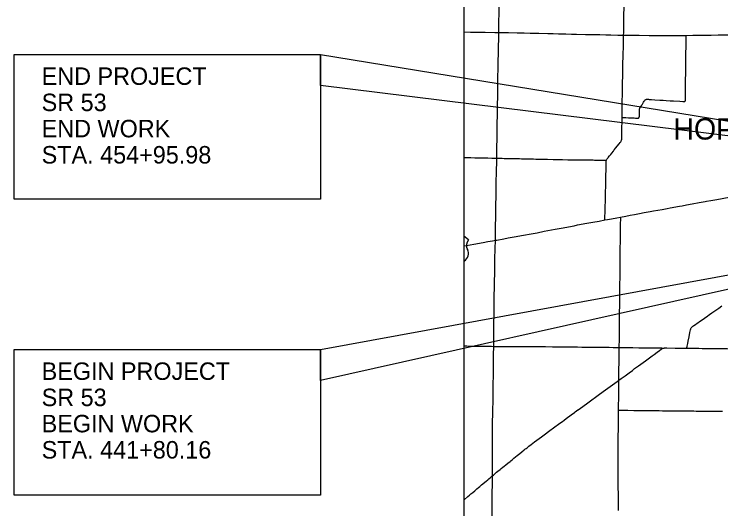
# Model space of a CAD drawing. Extents: x 1772825 to 1773716, y 1138558 to 1139032.
# Drawn here: x 1773161.2 to 1773274.4, y 1138810.8 to 1138890.1 of the extents above; entities that cross this region are included whole.
import ezdxf

# ---------------------------------------------------------------- set-up
doc = ezdxf.new("R2010")
doc.units = 0
for name, color, linetype in [('GM_X_County', 7, 'Continuous'), ('GM_X_County_Road', 7, 'Continuous'), ('GM_X_Township_Road', 7, 'Continuous'), ('GM_X_Township_Text', 7, 'Continuous'), ('GM_X_US_Route', 7, 'Continuous'), ('GM_X_US_Shield', 7, 'Continuous'), ('SH_Text', 7, 'Continuous')]:
    doc.layers.add(name, color=color, linetype=linetype)

msp = doc.modelspace()

# ---------------------------------------------------------------- linework, layer by layer
at = {"layer": 'GM_X_County'}
msp.add_lwpolyline([(1773505.23, 1138706), (1773505.23, 1138955.63), (1773233.23, 1138955.63), (1773233.23, 1138706.53)], dxfattribs=at)
at = {"layer": 'GM_X_County_Road'}
for points in [[(1773238.81, 1138887.14), (1773238.84, 1138888), (1773238.86, 1138889.19), (1773238.87, 1138889.84), (1773238.88, 1138890.17), (1773238.89, 1138890.85), (1773238.91, 1138891.85), (1773238.93, 1138892.61), (1773238.93, 1138893), (1773238.95, 1138893.91), (1773238.96, 1138894.73), (1773238.97, 1138895.36), (1773238.98, 1138895.88), (1773238.99, 1138896.4), (1773239, 1138896.7)], [(1773238.5, 1138866.99), (1773238.51, 1138867.73), (1773238.53, 1138868.87), (1773238.55, 1138869.98), (1773238.58, 1138871.59), (1773238.58, 1138872.09), (1773238.59, 1138872.83), (1773238.6, 1138873.61), (1773238.63, 1138874.75), (1773238.63, 1138875.22), (1773238.63, 1138875.64), (1773238.65, 1138876.78), (1773238.67, 1138878.39), (1773238.69, 1138879.49), (1773238.73, 1138881.84), (1773238.74, 1138882.24), (1773238.75, 1138882.74), (1773238.76, 1138883.53), (1773238.76, 1138884.03), (1773238.81, 1138886.96), (1773238.81, 1138887.04), (1773238.81, 1138887.14)], [(1773233.23, 1138867.09), (1773233.38, 1138867.08), (1773234.37, 1138867.07), (1773235.01, 1138867.06), (1773235.99, 1138867.04), (1773237.09, 1138867.02), (1773237.7, 1138867.01), (1773238.5, 1138866.99)], [(1773238.28, 1138853.83), (1773238.28, 1138854.32), (1773238.29, 1138855.16), (1773238.31, 1138855.88), (1773238.32, 1138856.59), (1773238.33, 1138857.05), (1773238.36, 1138858.8), (1773238.37, 1138859.61), (1773238.39, 1138860.74), (1773238.41, 1138862.14), (1773238.43, 1138862.96), (1773238.46, 1138864.91), (1773238.5, 1138866.47), (1773238.5, 1138866.99)], [(1773238.01, 1138836.83), (1773238.02, 1138837.31), (1773238.03, 1138838.12), (1773238.05, 1138839.42), (1773238.06, 1138840.46), (1773238.07, 1138841.97), (1773238.1, 1138843.68), (1773238.11, 1138844.97), (1773238.13, 1138846.23), (1773238.16, 1138847.64), (1773238.17, 1138848.12), (1773238.19, 1138848.54), (1773238.21, 1138849.39), (1773238.21, 1138850.09), (1773238.22, 1138850.86), (1773238.25, 1138852.45), (1773238.27, 1138853.01), (1773238.28, 1138853.34), (1773238.28, 1138853.74), (1773238.28, 1138853.83)], [(1773268.89, 1138836.55), (1773268.93, 1138836.62), (1773268.96, 1138836.7), (1773268.99, 1138836.77), (1773269.02, 1138836.86), (1773269.1, 1138837.27), (1773269.17, 1138837.66), (1773269.31, 1138838.36), (1773269.45, 1138839.04), (1773269.54, 1138839.48), (1773269.57, 1138839.62), (1773269.61, 1138839.72), (1773269.65, 1138839.79), (1773269.68, 1138839.85), (1773269.74, 1138839.91), (1773269.81, 1138839.98), (1773269.89, 1138840.05), (1773270.01, 1138840.14), (1773270.4, 1138840.39), (1773270.57, 1138840.51), (1773271.16, 1138840.91), (1773271.56, 1138841.2), (1773272.01, 1138841.51), (1773272.23, 1138841.67), (1773272.38, 1138841.78), (1773272.6, 1138841.93), (1773272.95, 1138842.18), (1773274.08, 1138842.98), (1773274.57, 1138843.34)], [(1773237.87, 1138826.78), (1773237.88, 1138826.88), (1773237.89, 1138826.97), (1773237.9, 1138827.2), (1773237.92, 1138827.5), (1773237.93, 1138827.96), (1773237.94, 1138829.45), (1773237.95, 1138830.6), (1773237.96, 1138832.32), (1773237.97, 1138833.08), (1773237.98, 1138834.2), (1773238, 1138835.46), (1773238.01, 1138836.83)], [(1773258.06, 1138831.4), (1773258.42, 1138831.67), (1773259.05, 1138832.13), (1773259.69, 1138832.6), (1773260.23, 1138832.99), (1773260.59, 1138833.26), (1773261.19, 1138833.7), (1773262.34, 1138834.54), (1773262.77, 1138834.86), (1773263.4, 1138835.31), (1773263.72, 1138835.55), (1773264.21, 1138835.91), (1773264.58, 1138836.18), (1773264.85, 1138836.38), (1773264.96, 1138836.45), (1773265.06, 1138836.5), (1773265.14, 1138836.54)], [(1773265.14, 1138836.54), (1773265.22, 1138836.56), (1773265.29, 1138836.57), (1773265.34, 1138836.58), (1773265.41, 1138836.59), (1773265.51, 1138836.59), (1773265.63, 1138836.59), (1773265.74, 1138836.59), (1773267.07, 1138836.56), (1773267.9, 1138836.55), (1773268.6, 1138836.55), (1773268.89, 1138836.55)], [(1773268.89, 1138836.55), (1773269.44, 1138836.54), (1773270.02, 1138836.53), (1773270.49, 1138836.52), (1773270.87, 1138836.52), (1773271.41, 1138836.51), (1773271.87, 1138836.51), (1773272.4, 1138836.5), (1773272.7, 1138836.5), (1773273.42, 1138836.49), (1773274.37, 1138836.48), (1773275, 1138836.48), (1773275.4, 1138836.47), (1773276.27, 1138836.46), (1773277.57, 1138836.45), (1773278.02, 1138836.45), (1773278.21, 1138836.45)], [(1773251.5, 1138826.64), (1773251.55, 1138826.68), (1773252.27, 1138827.2), (1773253.11, 1138827.81), (1773254.95, 1138829.15), (1773255.92, 1138829.85), (1773257.39, 1138830.92), (1773257.77, 1138831.2), (1773258.06, 1138831.4)], [(1773258.02, 1138826.61), (1773258.02, 1138827.44), (1773258.03, 1138828.43), (1773258.04, 1138829.74), (1773258.05, 1138830.39), (1773258.06, 1138831.13), (1773258.06, 1138831.4)], [(1773237.82, 1138816.1), (1773237.82, 1138816.25), (1773237.82, 1138816.71), (1773237.82, 1138817.4), (1773237.83, 1138817.87), (1773237.83, 1138819.43), (1773237.83, 1138820.75), (1773237.83, 1138821.54), (1773237.83, 1138822.92), (1773237.83, 1138823.61), (1773237.84, 1138824.32), (1773237.85, 1138826.38), (1773237.86, 1138826.62), (1773237.87, 1138826.78)], [(1773237.82, 1138816.1), (1773237.96, 1138816.22), (1773238.19, 1138816.42), (1773238.47, 1138816.65), (1773238.7, 1138816.84), (1773239.04, 1138817.12), (1773239.2, 1138817.25), (1773239.5, 1138817.48), (1773239.7, 1138817.65), (1773239.97, 1138817.86), (1773240.26, 1138818.1), (1773240.64, 1138818.41), (1773240.76, 1138818.51), (1773241.01, 1138818.71), (1773241.23, 1138818.9), (1773241.49, 1138819.11), (1773241.75, 1138819.32), (1773242.18, 1138819.66), (1773242.52, 1138819.94), (1773242.9, 1138820.25), (1773243.02, 1138820.34), (1773243.2, 1138820.48), (1773243.35, 1138820.6), (1773243.64, 1138820.82), (1773244.02, 1138821.12), (1773244.55, 1138821.53), (1773245.65, 1138822.35), (1773246.29, 1138822.84), (1773246.77, 1138823.19), (1773247.79, 1138823.93), (1773248.39, 1138824.37), (1773248.74, 1138824.62), (1773249.01, 1138824.82), (1773249.28, 1138825.01), (1773249.64, 1138825.29), (1773250.41, 1138825.84), (1773250.96, 1138826.25)], [(1773250.96, 1138826.25), (1773251.06, 1138826.32), (1773251.5, 1138826.64)], [(1773258.01, 1138810.53), (1773258.01, 1138811.28), (1773258, 1138811.65), (1773258, 1138811.98), (1773258, 1138812.39), (1773257.99, 1138812.71), (1773257.99, 1138812.9), (1773257.99, 1138813.09), (1773257.98, 1138813.51), (1773257.97, 1138813.89), (1773257.97, 1138814.42), (1773257.97, 1138814.76), (1773257.96, 1138815.8), (1773257.96, 1138816.21), (1773257.95, 1138816.76), (1773257.95, 1138817.5), (1773257.95, 1138818.29), (1773257.96, 1138818.81), (1773257.96, 1138819.33), (1773257.96, 1138819.83), (1773257.96, 1138820.3), (1773257.96, 1138821.47), (1773257.97, 1138822.64), (1773257.98, 1138823.35), (1773258, 1138824.89), (1773258.01, 1138826.38), (1773258.02, 1138826.61)], [(1773233.23, 1138812.24), (1773233.26, 1138812.26), (1773233.86, 1138812.75), (1773234.15, 1138813), (1773234.36, 1138813.18), (1773234.65, 1138813.42), (1773234.99, 1138813.71), (1773235.32, 1138813.99), (1773235.59, 1138814.22), (1773235.8, 1138814.4), (1773236.06, 1138814.62), (1773236.28, 1138814.81), (1773236.57, 1138815.05), (1773236.8, 1138815.24), (1773237.06, 1138815.47), (1773237.26, 1138815.63), (1773237.5, 1138815.83), (1773237.73, 1138816.03), (1773237.82, 1138816.1)]]:
    msp.add_lwpolyline(points, dxfattribs=at)
at = {"layer": 'GM_X_Township_Road'}
for points in [[(1773258.82, 1138886.7), (1773258.83, 1138887.1), (1773258.84, 1138887.62), (1773258.85, 1138888.35), (1773258.87, 1138889.23), (1773258.88, 1138890.08), (1773258.9, 1138890.96), (1773258.92, 1138891.82), (1773258.94, 1138892.77), (1773258.95, 1138893.55), (1773258.95, 1138894.07), (1773258.97, 1138894.71), (1773258.98, 1138895.27), (1773258.99, 1138895.93), (1773259, 1138896.45), (1773259.01, 1138896.9), (1773259.01, 1138896.97)], [(1773233.23, 1138887.21), (1773234.32, 1138887.2), (1773235.07, 1138887.18), (1773235.86, 1138887.18), (1773236.65, 1138887.17), (1773238.21, 1138887.15), (1773238.81, 1138887.14)], [(1773238.81, 1138887.14), (1773239.06, 1138887.13), (1773239.67, 1138887.12), (1773240.39, 1138887.1), (1773241.79, 1138887.08), (1773242.89, 1138887.05), (1773243.88, 1138887.03), (1773244.54, 1138887.02), (1773244.94, 1138887.01), (1773245.24, 1138887), (1773246.69, 1138886.97), (1773247.54, 1138886.95), (1773248.37, 1138886.93), (1773249.55, 1138886.9), (1773250.47, 1138886.88), (1773251.3, 1138886.86), (1773252.7, 1138886.83), (1773253.38, 1138886.81), (1773254.3, 1138886.79), (1773255.02, 1138886.78), (1773255.99, 1138886.76), (1773256.77, 1138886.74), (1773257.88, 1138886.72), (1773258.82, 1138886.7)], [(1773258.57, 1138873.52), (1773258.59, 1138874.59), (1773258.61, 1138875.68), (1773258.61, 1138876.38), (1773258.62, 1138876.93), (1773258.64, 1138877.93), (1773258.66, 1138879.12), (1773258.68, 1138880.13), (1773258.7, 1138880.85), (1773258.71, 1138881.51), (1773258.72, 1138882.19), (1773258.74, 1138883.22), (1773258.79, 1138885.28), (1773258.8, 1138886), (1773258.82, 1138886.7)], [(1773258.57, 1138873.52), (1773259.15, 1138873.49), (1773259.6, 1138873.47), (1773260.1, 1138873.45), (1773260.38, 1138873.44), (1773260.52, 1138873.43), (1773260.71, 1138873.42), (1773260.83, 1138873.4), (1773260.94, 1138873.39), (1773261.01, 1138873.38), (1773261.09, 1138873.39), (1773261.15, 1138873.4), (1773261.18, 1138873.42), (1773261.21, 1138873.44), (1773261.24, 1138873.46), (1773261.27, 1138873.48), (1773261.29, 1138873.52), (1773261.31, 1138873.55), (1773261.32, 1138873.57), (1773261.33, 1138873.62), (1773261.34, 1138873.68), (1773261.35, 1138873.76), (1773261.35, 1138873.92), (1773261.36, 1138874.1), (1773261.37, 1138874.54), (1773261.37, 1138874.73), (1773261.38, 1138874.8), (1773261.39, 1138874.88), (1773261.4, 1138874.93), (1773261.41, 1138874.97), (1773261.44, 1138875.05), (1773261.47, 1138875.1), (1773261.51, 1138875.16), (1773261.62, 1138875.31), (1773261.68, 1138875.4), (1773261.75, 1138875.51), (1773261.84, 1138875.64), (1773261.94, 1138875.83), (1773262.01, 1138875.97), (1773262.09, 1138876.1), (1773262.15, 1138876.2), (1773262.2, 1138876.27), (1773262.26, 1138876.32), (1773262.3, 1138876.35), (1773262.36, 1138876.39), (1773262.41, 1138876.41), (1773262.46, 1138876.42), (1773262.51, 1138876.43), (1773262.57, 1138876.43), (1773262.64, 1138876.43), (1773262.78, 1138876.42), (1773262.9, 1138876.41), (1773263.26, 1138876.38), (1773263.81, 1138876.34), (1773264.61, 1138876.29), (1773265.18, 1138876.26), (1773265.64, 1138876.23), (1773266.25, 1138876.19), (1773266.81, 1138876.15), (1773267.8, 1138876.1), (1773268.3, 1138876.06), (1773268.49, 1138876.05), (1773268.54, 1138876.05), (1773268.59, 1138876.06), (1773268.62, 1138876.07), (1773268.65, 1138876.09), (1773268.67, 1138876.11), (1773268.67, 1138876.11), (1773268.69, 1138876.14), (1773268.7, 1138876.17), (1773268.72, 1138876.22), (1773268.72, 1138876.28), (1773268.72, 1138876.4), (1773268.72, 1138876.67), (1773268.72, 1138876.86), (1773268.72, 1138877.15), (1773268.73, 1138878.28), (1773268.75, 1138879.05), (1773268.75, 1138879.68), (1773268.76, 1138880.41), (1773268.77, 1138881.02), (1773268.79, 1138881.86), (1773268.79, 1138882.24), (1773268.8, 1138882.87), (1773268.81, 1138883.38), (1773268.81, 1138883.94), (1773268.82, 1138884.74), (1773268.83, 1138885.44), (1773268.84, 1138885.99), (1773268.84, 1138886.43), (1773268.83, 1138886.66)], [(1773258.82, 1138886.7), (1773259.31, 1138886.69), (1773260.16, 1138886.69), (1773261.33, 1138886.68), (1773262.9, 1138886.66), (1773264.13, 1138886.65), (1773265.02, 1138886.66), (1773265.76, 1138886.65)], [(1773265.76, 1138886.65), (1773265.86, 1138886.65), (1773266.57, 1138886.66), (1773267.58, 1138886.65), (1773268.18, 1138886.66), (1773268.83, 1138886.66)], [(1773268.83, 1138886.66), (1773269.92, 1138886.68), (1773270.38, 1138886.68), (1773270.83, 1138886.69), (1773271.33, 1138886.69), (1773272.15, 1138886.7), (1773272.84, 1138886.71), (1773273.96, 1138886.73), (1773274.46, 1138886.74), (1773276.12, 1138886.77), (1773277.78, 1138886.8), (1773278.7, 1138886.81), (1773278.92, 1138886.81)], [(1773256.06, 1138866.66), (1773256.06, 1138866.66), (1773256.09, 1138866.73), (1773256.14, 1138866.81), (1773256.18, 1138866.87), (1773256.23, 1138866.94), (1773256.28, 1138867), (1773256.34, 1138867.07), (1773256.55, 1138867.35), (1773256.77, 1138867.6), (1773256.93, 1138867.81), (1773257.18, 1138868.13), (1773257.31, 1138868.3), (1773257.59, 1138868.66), (1773257.77, 1138868.89), (1773258.1, 1138869.29), (1773258.27, 1138869.51), (1773258.32, 1138869.57), (1773258.36, 1138869.63), (1773258.41, 1138869.72), (1773258.45, 1138869.79), (1773258.48, 1138869.85), (1773258.49, 1138869.9), (1773258.52, 1138869.97), (1773258.53, 1138870.03), (1773258.54, 1138870.1), (1773258.54, 1138870.15), (1773258.55, 1138870.22), (1773258.55, 1138870.29), (1773258.55, 1138870.6), (1773258.55, 1138871.35), (1773258.56, 1138871.74), (1773258.56, 1138872.07), (1773258.57, 1138872.59), (1773258.57, 1138873.52)], [(1773238.5, 1138866.99), (1773238.73, 1138866.98), (1773239.38, 1138866.97), (1773239.67, 1138866.96), (1773240.11, 1138866.95), (1773240.41, 1138866.95), (1773240.62, 1138866.94), (1773241.12, 1138866.93), (1773241.54, 1138866.92), (1773242.15, 1138866.91), (1773242.49, 1138866.9), (1773242.75, 1138866.9), (1773243.26, 1138866.88), (1773243.88, 1138866.87), (1773244.41, 1138866.86), (1773244.76, 1138866.85), (1773245.27, 1138866.84), (1773245.64, 1138866.83), (1773246.05, 1138866.82), (1773246.65, 1138866.81), (1773247.54, 1138866.79), (1773248.26, 1138866.77), (1773249.01, 1138866.76), (1773249.88, 1138866.74), (1773250.57, 1138866.73), (1773251.11, 1138866.73), (1773251.95, 1138866.72), (1773252.56, 1138866.71), (1773253.23, 1138866.7), (1773253.92, 1138866.7), (1773254.15, 1138866.69), (1773254.7, 1138866.69), (1773255.38, 1138866.68), (1773255.94, 1138866.66), (1773256.06, 1138866.66)], [(1773255.82, 1138857.09), (1773255.82, 1138857.24), (1773255.83, 1138857.68), (1773255.85, 1138858.22), (1773255.87, 1138859.27), (1773255.9, 1138860.09), (1773255.92, 1138861.38), (1773255.96, 1138862.68), (1773255.97, 1138863.41), (1773255.99, 1138864.28), (1773256, 1138865.06), (1773256.01, 1138865.36), (1773256.01, 1138865.98), (1773256.01, 1138866.18), (1773256.02, 1138866.29), (1773256.02, 1138866.43), (1773256.03, 1138866.54), (1773256.04, 1138866.6), (1773256.06, 1138866.66)], [(1773258.12, 1138836.66), (1773258.12, 1138836.66), (1773258.13, 1138837.03), (1773258.14, 1138837.67), (1773258.14, 1138838.24), (1773258.14, 1138839.01), (1773258.15, 1138839.81), (1773258.16, 1138840.85), (1773258.17, 1138841.58), (1773258.18, 1138842.17), (1773258.18, 1138842.68), (1773258.19, 1138842.96), (1773258.19, 1138843.85), (1773258.21, 1138845.03), (1773258.23, 1138846.72), (1773258.25, 1138847.92), (1773258.26, 1138848.89), (1773258.26, 1138849.8), (1773258.27, 1138850.72), (1773258.29, 1138852.41), (1773258.31, 1138853.78), (1773258.32, 1138854.41), (1773258.32, 1138855.2), (1773258.33, 1138856.06), (1773258.34, 1138856.58), (1773258.35, 1138857.1), (1773258.35, 1138857.2), (1773258.35, 1138857.31), (1773258.34, 1138857.44), (1773258.33, 1138857.56)], [(1773233.23, 1138836.91), (1773233.69, 1138836.9), (1773234.18, 1138836.89), (1773234.46, 1138836.89), (1773235.45, 1138836.88), (1773236.11, 1138836.86), (1773236.72, 1138836.85), (1773237.67, 1138836.84), (1773238.01, 1138836.83)], [(1773238.01, 1138836.83), (1773238.08, 1138836.83), (1773238.4, 1138836.83), (1773239.17, 1138836.83), (1773239.77, 1138836.83), (1773240.51, 1138836.83), (1773241.08, 1138836.83), (1773241.69, 1138836.82), (1773242.02, 1138836.82), (1773242.89, 1138836.82), (1773243.43, 1138836.81), (1773243.98, 1138836.82), (1773244.73, 1138836.81), (1773245.37, 1138836.8), (1773245.94, 1138836.79), (1773246.3, 1138836.79), (1773247.44, 1138836.78), (1773248.04, 1138836.77), (1773248.53, 1138836.77), (1773248.84, 1138836.76), (1773248.95, 1138836.76), (1773249.32, 1138836.76), (1773250.01, 1138836.76), (1773250.44, 1138836.75), (1773250.87, 1138836.75), (1773251.46, 1138836.74), (1773252.11, 1138836.73), (1773252.69, 1138836.72), (1773253.04, 1138836.72), (1773253.69, 1138836.71), (1773254.11, 1138836.71), (1773254.83, 1138836.7), (1773255.43, 1138836.69), (1773255.97, 1138836.68), (1773256.51, 1138836.68), (1773257.13, 1138836.67), (1773257.54, 1138836.67), (1773258.12, 1138836.66)], [(1773258.06, 1138831.4), (1773258.06, 1138831.58), (1773258.06, 1138831.9), (1773258.08, 1138833.23), (1773258.09, 1138834.13), (1773258.1, 1138834.86), (1773258.11, 1138836.06), (1773258.12, 1138836.66)], [(1773258.12, 1138836.66), (1773259.55, 1138836.64), (1773260.31, 1138836.64), (1773261.26, 1138836.62), (1773261.77, 1138836.62), (1773262.91, 1138836.61), (1773264.09, 1138836.59), (1773264.4, 1138836.59), (1773264.69, 1138836.59), (1773264.9, 1138836.58), (1773264.97, 1138836.57), (1773265.03, 1138836.57), (1773265.07, 1138836.56), (1773265.11, 1138836.55), (1773265.14, 1138836.54)], [(1773258.02, 1138826.61), (1773258.36, 1138826.6), (1773258.88, 1138826.6), (1773259.48, 1138826.59), (1773260.44, 1138826.57), (1773261.85, 1138826.56), (1773262.18, 1138826.56), (1773262.77, 1138826.54), (1773263.12, 1138826.54), (1773263.46, 1138826.54), (1773263.98, 1138826.53), (1773264.23, 1138826.53), (1773264.51, 1138826.53), (1773265.03, 1138826.52), (1773265.52, 1138826.51), (1773265.67, 1138826.51), (1773265.9, 1138826.51), (1773266.21, 1138826.5), (1773266.38, 1138826.5), (1773266.65, 1138826.5), (1773266.95, 1138826.5), (1773267.29, 1138826.49), (1773267.75, 1138826.49), (1773268.04, 1138826.49), (1773268.15, 1138826.49), (1773268.26, 1138826.49), (1773268.65, 1138826.49), (1773268.92, 1138826.49), (1773269.15, 1138826.49), (1773269.4, 1138826.49), (1773269.72, 1138826.49), (1773270.09, 1138826.48), (1773270.45, 1138826.47), (1773270.79, 1138826.46), (1773271.38, 1138826.47), (1773271.73, 1138826.47), (1773271.99, 1138826.47), (1773272.17, 1138826.46), (1773272.67, 1138826.46), (1773273.14, 1138826.46), (1773273.43, 1138826.46), (1773273.69, 1138826.46), (1773274.19, 1138826.45), (1773274.67, 1138826.45)], [(1773237.72, 1138806.46), (1773237.73, 1138806.59), (1773237.74, 1138808.04), (1773237.75, 1138809.01), (1773237.76, 1138810.19), (1773237.78, 1138811.51), (1773237.79, 1138812.24), (1773237.79, 1138812.95), (1773237.79, 1138813.73), (1773237.8, 1138814.33), (1773237.8, 1138814.9), (1773237.81, 1138815.82), (1773237.82, 1138816.1)]]:
    msp.add_lwpolyline(points, dxfattribs=at)
at = {"layer": 'GM_X_US_Route'}
msp.add_lwpolyline([(1773233.23, 1138852.92), (1773233.65, 1138853), (1773234.81, 1138853.21), (1773236.31, 1138853.48), (1773237.07, 1138853.62), (1773237.82, 1138853.75), (1773238.28, 1138853.83), (1773238.49, 1138853.87), (1773239.63, 1138854.08), (1773240.34, 1138854.21), (1773241.28, 1138854.38), (1773242.8, 1138854.65), (1773244.03, 1138854.87), (1773244.97, 1138855.05), (1773246.12, 1138855.27), (1773247.88, 1138855.61), (1773249.13, 1138855.84), (1773249.99, 1138856), (1773250.89, 1138856.17), (1773251.46, 1138856.28), (1773252.94, 1138856.55), (1773253.91, 1138856.73), (1773254.88, 1138856.91), (1773255.82, 1138857.09), (1773256.25, 1138857.17), (1773256.86, 1138857.28), (1773257.71, 1138857.44), (1773258.33, 1138857.56), (1773259.15, 1138857.71), (1773259.87, 1138857.84), (1773260.54, 1138857.96), (1773261.34, 1138858.12), (1773262.09, 1138858.26), (1773263.07, 1138858.44), (1773263.59, 1138858.53), (1773265.01, 1138858.78), (1773265.81, 1138858.93), (1773266.27, 1138859.01), (1773267.76, 1138859.29), (1773268.21, 1138859.37), (1773268.88, 1138859.5), (1773269.81, 1138859.66), (1773270.94, 1138859.86), (1773271.58, 1138859.97), (1773271.87, 1138860.03), (1773272.11, 1138860.08), (1773272.8, 1138860.19), (1773273.75, 1138860.36), (1773275.72, 1138860.72)], dxfattribs=at)
at = {"layer": 'GM_X_US_Shield'}
for p, q in [((1773233.97, 1138853.9), (1773233.23, 1138854.5)), ((1773233.23, 1138854.5), (1773233.23, 1138850.48))]:
    msp.add_line(p, q, dxfattribs=at)
for centre, start_param, end_param in [((1773235.55, 1138853.02), 5.672304, 6.727422), ((1773232.07, 1138851.71), 2.217231, 3.580859)]:
    msp.add_ellipse(centre, major_axis=(-1.92, 0), ratio=0.8, start_param=start_param, end_param=end_param, dxfattribs=at)
at = {"layer": 'SH_Text'}
for points in [[(1773161.21, 1138883.59), (1773210.29, 1138883.59), (1773210.29, 1138860.43), (1773161.21, 1138860.43)], [(1773210.29, 1138883.59), (1773335.51, 1138863.13), (1773210.29, 1138878.64)], [(1773210.29, 1138836.32), (1773332.53, 1138858.71), (1773210.29, 1138831.38)], [(1773161.21, 1138836.32), (1773210.29, 1138836.32), (1773210.29, 1138813.01), (1773161.21, 1138813.01)]]:
    msp.add_lwpolyline(points, close=True, dxfattribs=at)

# ---------------------------------------------------------------- texts
at = {"layer": 'GM_X_Township_Text'}
msp.add_text('HOPEWELL', height=3.409, rotation=0, dxfattribs=at).set_placement((1773266.8, 1138869.97))
at = {"layer": 'SH_Text'}
for s, p in [('END PROJECT', (1773165.62, 1138878.73)), ('SR 53', (1773165.62, 1138874.53)), ('END WORK', (1773165.62, 1138870.33)), ('STA. 454+95.98', (1773165.62, 1138866.13)), ('BEGIN PROJECT', (1773165.62, 1138831.46)), ('SR 53', (1773165.62, 1138827.26)), ('BEGIN WORK', (1773165.62, 1138823.06)), ('STA. 441+80.16', (1773165.62, 1138818.86))]:
    msp.add_text(s, height=2.8, dxfattribs=at).set_placement(p)

doc.saveas('drawing.dxf')
